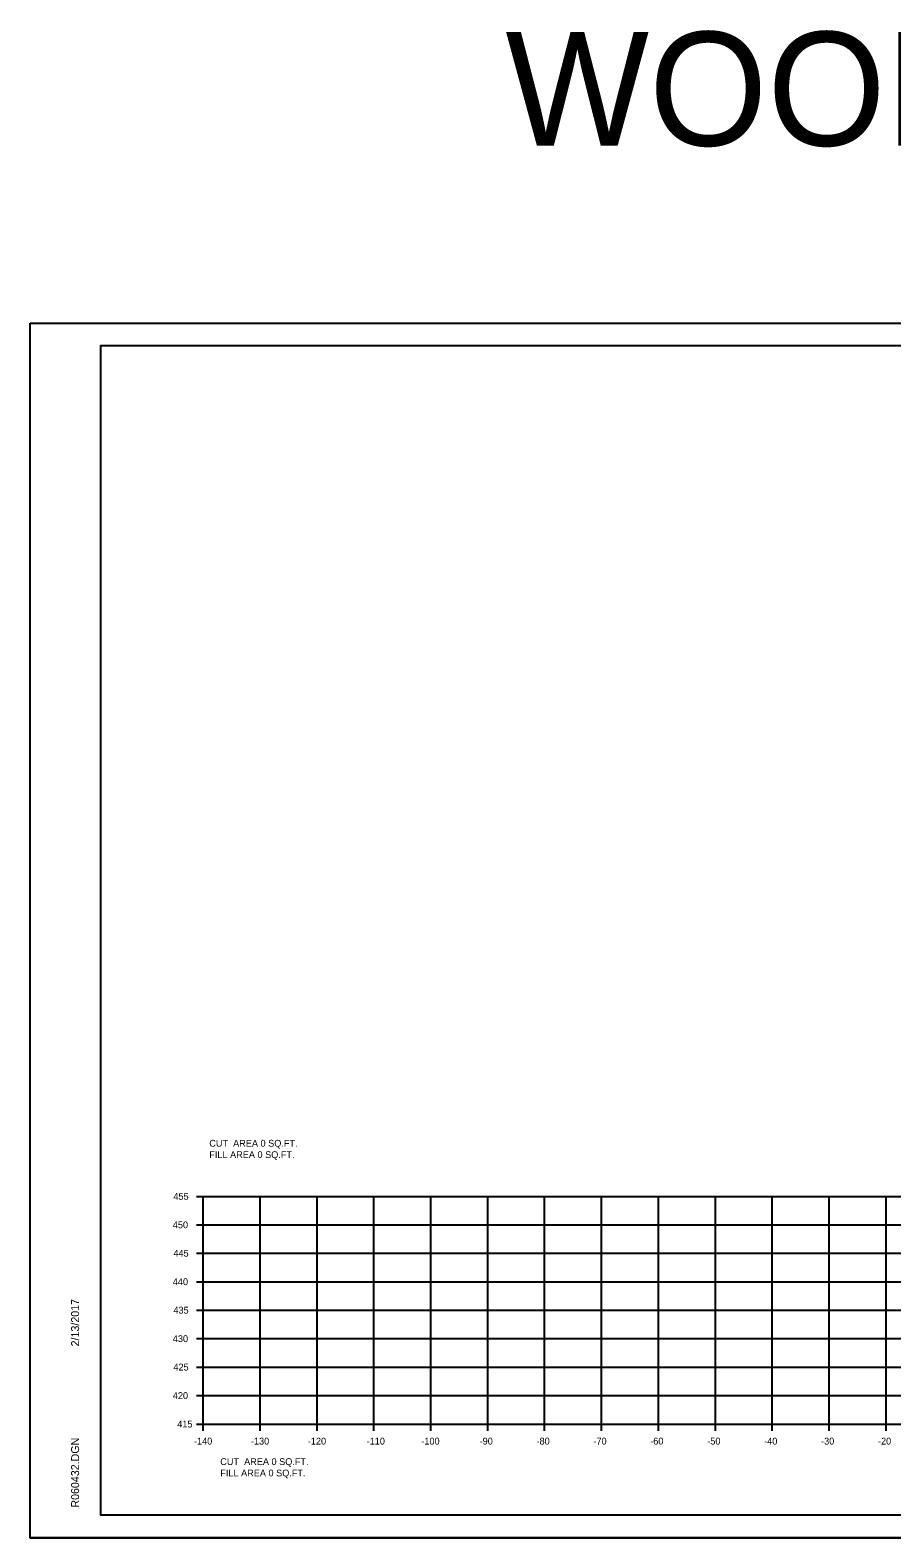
# Model space of a CAD drawing. Extents: x 1538688 to 1540766, y 656250 to 671912.
# Drawn here: x 1540432.5 to 1540584, y 656697.4 to 656962.2 of the extents above; entities that cross this region are included whole.
import ezdxf

# ---------------------------------------------------------------- set-up
doc = ezdxf.new("R2010")
doc.units = 0
for name, color, linetype in [('20', 7, 'Continuous'), ('22', 7, 'Continuous'), ('26', 7, 'Continuous'), ('Borings', 7, 'Continuous'), ('Horizontal Alignment', 7, 'Continuous'), ('RipRap', 7, 'Continuous')]:
    doc.layers.add(name, color=color, linetype=linetype)

msp = doc.modelspace()

# ---------------------------------------------------------------- linework, layer by layer
at = {"layer": '22'}
for p, q in [((1540462.94, 656757.38), (1540742.94, 656757.38)), ((1540462.94, 656717.38), (1540462.94, 656757.38)), ((1540472.94, 656717.38), (1540472.94, 656757.38)), ((1540482.94, 656717.38), (1540482.94, 656757.38)), ((1540492.94, 656717.38), (1540492.94, 656757.38)), ((1540502.94, 656717.38), (1540502.94, 656757.38)), ((1540512.94, 656717.38), (1540512.94, 656757.38)), ((1540522.94, 656717.38), (1540522.94, 656757.38)), ((1540532.94, 656717.38), (1540532.94, 656757.38)), ((1540542.94, 656717.38), (1540542.94, 656757.38)), ((1540552.94, 656717.38), (1540552.94, 656757.38)), ((1540562.94, 656717.38), (1540562.94, 656757.38)), ((1540572.94, 656717.38), (1540572.94, 656757.38)), ((1540582.94, 656717.38), (1540582.94, 656757.38)), ((1540462.94, 656752.38), (1540742.94, 656752.38)), ((1540462.94, 656747.38), (1540742.94, 656747.38)), ((1540462.94, 656742.38), (1540742.94, 656742.38)), ((1540462.94, 656737.38), (1540742.94, 656737.38)), ((1540462.94, 656732.38), (1540742.94, 656732.38)), ((1540462.94, 656727.38), (1540742.94, 656727.38)), ((1540462.94, 656722.38), (1540742.94, 656722.38)), ((1540462.94, 656717.38), (1540742.94, 656717.38))]:
    msp.add_line(p, q, dxfattribs=at)
at = {"layer": '26'}
for p, q in [((1540432.54, 656910.73), (1540765.87, 656910.73)), ((1540432.54, 656697.4), (1540765.87, 656697.4))]:
    msp.add_line(p, q, dxfattribs=at)
for points in [[(1540432.53, 656910.73), (1540765.87, 656910.73), (1540765.87, 656697.39), (1540432.53, 656697.39)], [(1540678.86, 656906.84), (1540678.86, 656896.96), (1540714.59, 656896.96), (1540714.59, 656894.04), (1540737.79, 656894.04), (1540737.79, 656869.7), (1540761.12, 656869.7), (1540761.12, 656701.38), (1540444.94, 656701.38), (1540444.94, 656906.84)]]:
    msp.add_lwpolyline(points, close=True, dxfattribs=at)
at = {"layer": 'Borings'}
for p, q in [((1540461.74, 656757.38), (1540462.94, 656757.38)), ((1540462.94, 656717.38), (1540462.94, 656757.38)), ((1540461.74, 656752.38), (1540462.94, 656752.38)), ((1540461.74, 656747.38), (1540462.94, 656747.38)), ((1540461.74, 656742.38), (1540462.94, 656742.38)), ((1540461.74, 656737.38), (1540462.94, 656737.38)), ((1540461.74, 656732.38), (1540462.94, 656732.38)), ((1540461.74, 656727.38), (1540462.94, 656727.38)), ((1540461.74, 656722.38), (1540462.94, 656722.38)), ((1540461.74, 656717.38), (1540462.94, 656717.38)), ((1540462.94, 656717.38), (1540742.94, 656717.38)), ((1540462.94, 656716.18), (1540462.94, 656717.38)), ((1540472.94, 656716.18), (1540472.94, 656717.38)), ((1540482.94, 656716.18), (1540482.94, 656717.38)), ((1540492.94, 656716.18), (1540492.94, 656717.38)), ((1540502.94, 656716.18), (1540502.94, 656717.38)), ((1540512.94, 656716.18), (1540512.94, 656717.38)), ((1540522.94, 656716.18), (1540522.94, 656717.38)), ((1540532.94, 656716.18), (1540532.94, 656717.38)), ((1540542.94, 656716.18), (1540542.94, 656717.38)), ((1540552.94, 656716.18), (1540552.94, 656717.38)), ((1540562.94, 656716.18), (1540562.94, 656717.38)), ((1540572.94, 656716.18), (1540572.94, 656717.38)), ((1540582.94, 656716.18), (1540582.94, 656717.38))]:
    msp.add_line(p, q, dxfattribs=at)
at = {"layer": 'RipRap'}
for p, q in [((1540444.94, 656906.84), (1540761.12, 656906.84)), ((1540444.94, 656701.38), (1540444.94, 656906.84)), ((1540444.94, 656701.38), (1540444.94, 656701.38)), ((1540761.12, 656701.38), (1540444.94, 656701.38))]:
    msp.add_line(p, q, dxfattribs=at)

# ---------------------------------------------------------------- texts
at = {"layer": '20'}
msp.add_text('WOODLORE', height=20, dxfattribs=at).set_placement((1540516.04, 656941.93))
at = {"layer": 'Horizontal Alignment'}
for s, p in [('CUT  AREA 0 SQ.FT.', (1540464.01, 656766.1)), ('FILL AREA 0 SQ.FT.', (1540464.01, 656764.1)), ('455', (1540457.7, 656756.78)), ('450', (1540457.6, 656751.78)), ('445', (1540457.7, 656746.78)), ('440', (1540457.6, 656741.78)), ('435', (1540457.7, 656736.78)), ('430', (1540457.6, 656731.78)), ('425', (1540457.7, 656726.78)), ('420', (1540457.6, 656721.78)), ('415', (1540458.38, 656716.78)), ('-140', (1540461.32, 656713.78)), ('-130', (1540471.32, 656713.78)), ('-120', (1540481.32, 656713.78)), ('-110', (1540491.66, 656713.78)), ('-100', (1540501.27, 656713.78)), ('-90', (1540511.51, 656713.78)), ('-80', (1540521.51, 656713.78)), ('-70', (1540531.51, 656713.78)), ('-60', (1540541.49, 656713.78)), ('-50', (1540551.51, 656713.78)), ('-40', (1540561.51, 656713.78)), ('-30', (1540571.51, 656713.78)), ('-20', (1540581.51, 656713.78)), ('CUT  AREA 0 SQ.FT.', (1540465.94, 656710.18)), ('FILL AREA 0 SQ.FT.', (1540465.94, 656708.18))]:
    msp.add_text(s, height=1.2, dxfattribs=at).set_placement(p)
at = {"layer": 'RipRap'}
for s, p in [('2/13/2017', (1540441.13, 656731.02)), ('R060432.DGN', (1540441.13, 656702.7))]:
    msp.add_text(s, height=1.4, rotation=90, dxfattribs=at).set_placement(p)

doc.saveas('drawing.dxf')
